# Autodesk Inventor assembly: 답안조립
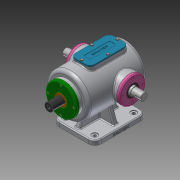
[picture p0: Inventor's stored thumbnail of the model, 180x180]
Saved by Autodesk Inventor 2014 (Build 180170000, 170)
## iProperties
Created: 2021-11
Part Number: 답안조립
Document SubType Name: Assembly
Designer: kb
Author: kb
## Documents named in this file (14)
- C:\Users\kb\Desktop\711106V1004\답안조립.iam
- C:\Users\kb\Desktop\711106V1004\답안본체.ipt
- C:\Users\kb\Desktop\711106V1004\베어링 6205.ipt
- 베어링 6205.ipt
- C:\Users\kb\Desktop\711106V1004\볼트 M4x0.7.ipt
- C:\Users\kb\Desktop\711106V1004\부시.ipt
- C:\Users\kb\Desktop\711106V1004\상부커버.ipt
- C:\Users\kb\Desktop\711106V1004\슬라이드 커버.ipt
- C:\Users\kb\Desktop\711106V1004\슬라이드.ipt
- C:\Users\kb\Desktop\711106V1004\오일실.ipt
- 오일실.ipt
- C:\Users\kb\Desktop\711106V1004\육각머리볼트 M4.ipt
- C:\Users\kb\Desktop\711106V1004\축 커버.ipt
- C:\Users\kb\Desktop\711106V1004\편심축.ipt
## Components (12 placed, 1 different names)
1. M4x0.7:3
2. M4x0.7:4
3. M4x0.7:5
4. M4x0.7:6
5. M4x0.7:1
6. M4x0.7:7
7. M4x0.7:8
8. M4x0.7:9
9. M4x0.7:2
10. M4x0.7:10
11. M4x0.7:11
12. M4x0.7:12
